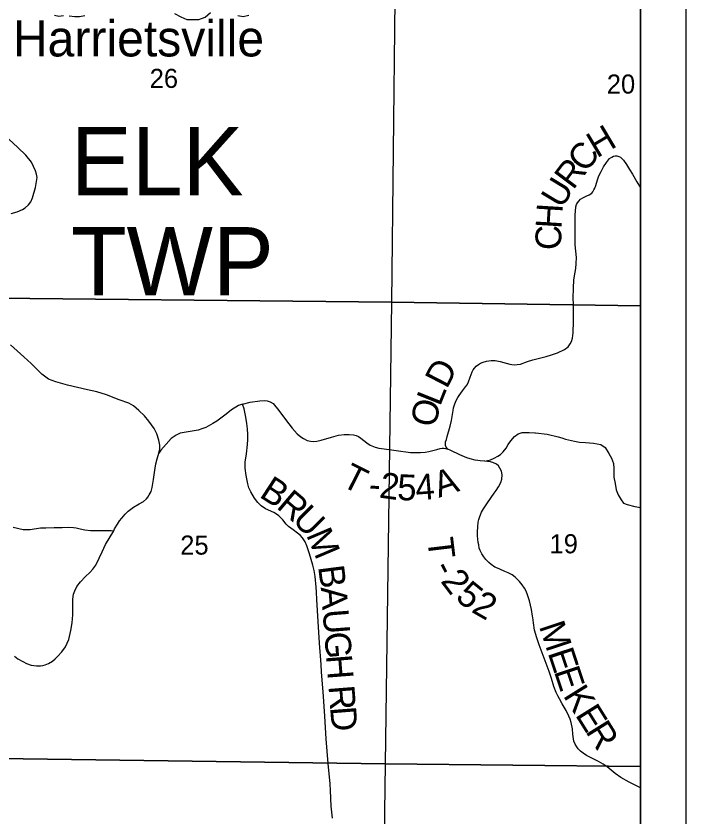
# Model space of a CAD drawing. Extents: x 0 to 34, y 0 to 22.
# Drawn here: x 7.529 to 9, y 17.691 to 19.45 of the extents above; entities that cross this region are included whole.
import ezdxf

# ---------------------------------------------------------------- set-up
doc = ezdxf.new("R2010")
doc.units = 0
for name, color, linetype in [('GM_X_Corporation', 7, 'Continuous'), ('GM_X_County_Road', 7, 'Continuous'), ('GM_X_County_Road_Text', 7, 'Continuous'), ('GM_X_Major_River', 7, 'Continuous'), ('GM_X_Section_Text', 7, 'Continuous'), ('GM_X_Township_Road', 7, 'Continuous'), ('GM_X_Township_Road_Text', 7, 'Continuous'), ('GM_X_Township_Text', 7, 'Continuous'), ('GM_X_Unincorporated_Text', 7, 'Continuous'), ('SH_Data', 7, 'Continuous')]:
    doc.layers.add(name, color=color, linetype=linetype)

msp = doc.modelspace()

# ---------------------------------------------------------------- linework, layer by layer
at = {"layer": 'GM_X_Corporation'}
for points in [[(8.3645, 19.8193), (8.353, 18.8213), (7.3418, 18.8315), (7.3548, 19.8302)], [(8.9, 18.8136), (8.9, 19.8133), (8.3645, 19.8193), (8.353, 18.8213)], [(8.353, 18.8213), (8.3394, 17.8082), (7.332, 17.8222), (7.3418, 18.8315)], [(8.9, 17.8023), (8.9, 18.8136), (8.353, 18.8213), (8.3394, 17.8082)], [(8.3394, 17.8082), (8.3265, 16.8592), (7.3376, 16.8759), (7.332, 17.8222)], [(8.9, 16.8493), (8.9, 17.8023), (8.3394, 17.8082), (8.3265, 16.8592)]]:
    msp.add_lwpolyline(points, close=True, dxfattribs=at)
at = {"layer": 'GM_X_County_Road'}
for points in [[(7.5185, 19.0165), (7.5317, 19.0201), (7.5428, 19.025), (7.5492, 19.0288), (7.5566, 19.0354), (7.5611, 19.042), (7.5653, 19.0508), (7.5717, 19.073), (7.5751, 19.0952), (7.5739, 19.1025), (7.5717, 19.1098), (7.5626, 19.1289), (7.5504, 19.1444), (7.5332, 19.1614), (7.5129, 19.1793)], [(8.2241, 17.6888), (8.2208, 17.7147), (8.2195, 17.7498), (8.2188, 17.7644), (8.2146, 17.8089), (8.2102, 17.8628), (8.2068, 17.9129), (8.2035, 17.9664), (8.2, 18.0095), (8.1989, 18.0259), (8.1956, 18.0731), (8.1926, 18.1205), (8.1897, 18.1689), (8.189, 18.1846), (8.1881, 18.1956), (8.1854, 18.2196), (8.1835, 18.2323), (8.1806, 18.2445), (8.1734, 18.2693), (8.1678, 18.2867), (8.1637, 18.2957), (8.1579, 18.3044), (8.1526, 18.3101), (8.147, 18.3147), (8.1371, 18.322), (8.1274, 18.3288), (8.1223, 18.3342), (8.1145, 18.3434), (8.1059, 18.3525), (8.1008, 18.3563), (8.0948, 18.3601), (8.0769, 18.3677), (8.0671, 18.3744), (8.0597, 18.3816), (8.0522, 18.3911), (8.0442, 18.4049), (8.0404, 18.4137), (8.0379, 18.4228), (8.0341, 18.4413), (8.0319, 18.4572), (8.0323, 18.4705), (8.0347, 18.4883), (8.0371, 18.509), (8.0376, 18.5199), (8.0377, 18.5307), (8.0373, 18.5438), (8.0358, 18.5553), (8.0337, 18.5693), (8.0296, 18.5877), (8.0261, 18.5974), (8.0176, 18.5948), (8.0019, 18.5852), (7.9906, 18.5759), (7.9785, 18.5669), (7.9695, 18.5601), (7.9614, 18.5549), (7.946, 18.5466), (7.9372, 18.5433), (7.9286, 18.5408), (7.8894, 18.5337), (7.8803, 18.5298), (7.8692, 18.5219), (7.8583, 18.5097), (7.8467, 18.4966), (7.8422, 18.4897), (7.8445, 18.4998), (7.8445, 18.5077), (7.8422, 18.5187), (7.8381, 18.5326), (7.8323, 18.5442), (7.8205, 18.5601), (7.8107, 18.5723), (7.7987, 18.5839), (7.7868, 18.5943), (7.7764, 18.5995), (7.7555, 18.6071), (7.7279, 18.6178), (7.7063, 18.6244), (7.6855, 18.6294), (7.642, 18.6392), (7.6163, 18.6464), (7.6005, 18.6528), (7.5858, 18.6636), (7.5619, 18.687), (7.5461, 18.7013), (7.517, 18.7276)]]:
    msp.add_lwpolyline(points, dxfattribs=at)
at = {"layer": 'GM_X_Major_River'}
for points in [[(7.6131, 19.4515), (7.6229, 19.4493), (7.6331, 19.4506)], [(7.6456, 19.4499), (7.6581, 19.4485), (7.668, 19.4486), (7.6801, 19.4507)], [(7.8768, 19.4554), (7.8905, 19.4476), (7.9042, 19.4424), (7.9174, 19.4418), (7.9303, 19.4419), (7.9442, 19.4474), (7.9562, 19.4578)], [(8.0161, 19.4512), (8.0279, 19.4487), (8.0403, 19.4518)]]:
    msp.add_lwpolyline(points, dxfattribs=at)
at = {"layer": 'GM_X_Township_Road'}
for points in [[(8.4768, 18.4991), (8.4733, 18.5035), (8.4719, 18.5068), (8.4716, 18.5106), (8.472, 18.5148), (8.4738, 18.52), (8.4759, 18.5263), (8.4824, 18.5495), (8.4851, 18.5615), (8.4866, 18.5705), (8.4887, 18.5835), (8.4896, 18.5894), (8.4907, 18.5941), (8.4922, 18.5986), (8.495, 18.6053), (8.4989, 18.6124), (8.5019, 18.6166), (8.5096, 18.627), (8.5162, 18.6353), (8.5195, 18.6402), (8.5224, 18.6466), (8.5261, 18.6569), (8.5304, 18.6685), (8.5326, 18.6729), (8.5353, 18.6767), (8.5392, 18.6807), (8.5442, 18.6848), (8.5485, 18.6876), (8.5543, 18.6901), (8.5619, 18.6921), (8.5719, 18.6935), (8.5812, 18.6933), (8.5922, 18.6912), (8.6052, 18.6879), (8.6135, 18.6856), (8.6177, 18.6849), (8.6234, 18.6843), (8.6292, 18.6844), (8.6363, 18.6856), (8.6521, 18.691), (8.6635, 18.6949), (8.6783, 18.6988), (8.6929, 18.7026), (8.7045, 18.7056), (8.7181, 18.71), (8.7334, 18.7174), (8.7415, 18.7237), (8.746, 18.73), (8.7486, 18.7352), (8.751, 18.7425), (8.7524, 18.7541), (8.753, 18.7799), (8.7527, 18.8173), (8.7526, 18.8305), (8.7528, 18.8526), (8.754, 18.8702), (8.7564, 18.8872), (8.7578, 18.8954), (8.7592, 18.9061), (8.7594, 18.9196), (8.757, 18.9471), (8.7564, 19.0012), (8.7566, 19.0133), (8.7573, 19.0216), (8.7584, 19.0306), (8.7599, 19.0356), (8.7618, 19.0395), (8.7648, 19.0435), (8.7686, 19.0473), (8.7738, 19.0507), (8.7825, 19.0549), (8.7877, 19.0574), (8.793, 19.0609), (8.7958, 19.0641), (8.798, 19.0681), (8.7997, 19.0721), (8.8018, 19.0774), (8.8056, 19.0901), (8.8089, 19.0986), (8.8136, 19.1081), (8.819, 19.1188), (8.8253, 19.1285), (8.8324, 19.1366), (8.8369, 19.1402), (8.8406, 19.1417), (8.8445, 19.1425), (8.8483, 19.1425), (8.8527, 19.1414), (8.8561, 19.1395), (8.8595, 19.137), (8.8629, 19.1334), (8.8697, 19.1234), (8.8758, 19.1131), (8.8822, 19.1027), (8.8924, 19.0855), (8.9, 19.0722)], [(8.0261, 18.5974), (8.0427, 18.6019), (8.0639, 18.6051), (8.0742, 18.6059), (8.0804, 18.6051), (8.0868, 18.6025), (8.0933, 18.5987), (8.1061, 18.5834), (8.1203, 18.5641), (8.1351, 18.5448), (8.146, 18.5328), (8.1542, 18.5262), (8.1604, 18.5219), (8.1681, 18.518), (8.1758, 18.5163), (8.1818, 18.5157), (8.1895, 18.5163), (8.1986, 18.5185), (8.2214, 18.5254), (8.2372, 18.5292), (8.2491, 18.5309), (8.2604, 18.531), (8.2701, 18.5302), (8.2757, 18.5287), (8.281, 18.5266), (8.2863, 18.5233), (8.2995, 18.5129), (8.3065, 18.5079), (8.3174, 18.5034), (8.3256, 18.5013), (8.3369, 18.4993), (8.3635, 18.496), (8.395, 18.4915), (8.4173, 18.4915), (8.4272, 18.4925), (8.4357, 18.4937), (8.4443, 18.4956), (8.453, 18.4984), (8.4601, 18.5003), (8.4644, 18.5011), (8.4681, 18.5013), (8.4718, 18.5006), (8.4768, 18.4991)], [(8.5585, 18.4726), (8.5642, 18.4736), (8.5707, 18.4753), (8.579, 18.479), (8.5871, 18.4835), (8.5926, 18.4871), (8.5986, 18.4928), (8.6054, 18.501), (8.6097, 18.5094), (8.6154, 18.5171), (8.6234, 18.5265), (8.6316, 18.5327), (8.6401, 18.5354), (8.6554, 18.5354), (8.6678, 18.5345), (8.6692, 18.5344)], [(8.6692, 18.5344), (8.6954, 18.5317), (8.719, 18.5258), (8.7272, 18.5234), (8.7353, 18.5206), (8.7554, 18.5161), (8.766, 18.5139), (8.779, 18.5135), (8.7966, 18.5117), (8.8127, 18.5091), (8.8228, 18.5024), (8.8309, 18.4892), (8.8361, 18.4788), (8.841, 18.4677), (8.8419, 18.456), (8.8419, 18.4371), (8.8445, 18.4235), (8.8467, 18.4096), (8.8508, 18.3988), (8.8579, 18.3877), (8.863, 18.3804), (8.871, 18.3771), (8.8876, 18.3727), (8.9, 18.3706)], [(8.5585, 18.4726), (8.5477, 18.4731), (8.5428, 18.4737), (8.537, 18.4748), (8.526, 18.4776), (8.519, 18.48), (8.5037, 18.4865), (8.4833, 18.496), (8.4768, 18.4991)], [(7.5257, 18.0444), (7.5331, 18.0388), (7.5438, 18.0325), (7.552, 18.0283), (7.5624, 18.0248), (7.574, 18.0233), (7.5828, 18.0231), (7.5881, 18.024), (7.5932, 18.0256), (7.6005, 18.0284), (7.6087, 18.0333), (7.6145, 18.0384), (7.6198, 18.0436), (7.6295, 18.0537), (7.6373, 18.0645), (7.6449, 18.0806), (7.6496, 18.1007), (7.6522, 18.1172), (7.6536, 18.135), (7.6539, 18.1471), (7.6535, 18.1588), (7.6535, 18.1693), (7.6553, 18.1802), (7.6577, 18.1876), (7.6622, 18.1971), (7.6702, 18.2076), (7.6814, 18.2192), (7.6906, 18.228), (7.6978, 18.235), (7.704, 18.244), (7.7116, 18.2598), (7.7178, 18.2736), (7.7255, 18.2896), (7.7435, 18.3194), (7.7454, 18.3238), (7.7515, 18.3343), (7.7561, 18.3414), (7.761, 18.3473), (7.7647, 18.352), (7.7688, 18.3563), (7.7754, 18.3626), (7.7811, 18.3673), (7.7872, 18.3716), (7.799, 18.3788), (7.8085, 18.3838), (7.8155, 18.3898), (7.8185, 18.3935), (7.8216, 18.3986), (7.8253, 18.4058), (7.828, 18.4149), (7.831, 18.4323), (7.8328, 18.4477), (7.8362, 18.4664), (7.8388, 18.4777), (7.8422, 18.4897)], [(8.6633, 18.1321), (8.6608, 18.147), (8.6567, 18.1658), (8.6523, 18.1792), (8.649, 18.1869), (8.6452, 18.1937), (8.64, 18.2013), (8.6345, 18.2082), (8.63, 18.2128), (8.6251, 18.2177), (8.6183, 18.2229), (8.6095, 18.2275), (8.6023, 18.2306), (8.591, 18.2352), (8.5858, 18.2372), (8.5806, 18.24), (8.5722, 18.2457), (8.567, 18.25), (8.5606, 18.2567), (8.5561, 18.2625), (8.5517, 18.2692), (8.548, 18.276), (8.5462, 18.2818), (8.5449, 18.2886), (8.5436, 18.2941), (8.5424, 18.3082), (8.5425, 18.3176), (8.5428, 18.3282), (8.544, 18.3389), (8.5452, 18.3444), (8.5474, 18.3507), (8.5513, 18.3606), (8.5554, 18.3679), (8.5641, 18.3809), (8.579, 18.4023), (8.5833, 18.4084), (8.5883, 18.4163), (8.5932, 18.4257), (8.5953, 18.433), (8.5961, 18.4424), (8.595, 18.4504), (8.5916, 18.4572), (8.5884, 18.462), (8.5837, 18.4656), (8.576, 18.4695), (8.5679, 18.4714), (8.5639, 18.472), (8.5585, 18.4726)], [(7.5228, 18.3273), (7.5444, 18.3226), (7.5601, 18.3226), (7.5826, 18.3259), (7.5946, 18.3262), (7.6126, 18.3266), (7.6299, 18.3272), (7.645, 18.3274), (7.655, 18.327), (7.6611, 18.3259), (7.6697, 18.3241), (7.6798, 18.322), (7.6921, 18.3205), (7.7075, 18.32), (7.7309, 18.3202), (7.7375, 18.3202), (7.7435, 18.3194)], [(8.9, 17.7551), (8.8756, 17.7676), (8.8571, 17.7778), (8.8445, 17.7867), (8.8266, 17.8016), (8.8182, 17.8072), (8.8079, 17.8129), (8.792, 17.8211), (8.7816, 17.8264), (8.7745, 17.8313), (8.7681, 17.836), (8.7634, 17.8408), (8.7602, 17.8451), (8.7563, 17.851), (8.7539, 17.8579), (8.7514, 17.8732), (8.7506, 17.8852), (8.748, 17.8985), (8.7458, 17.9059), (8.7428, 17.9128), (8.7367, 17.9251), (8.7279, 17.9399), (8.7221, 17.9507), (8.7183, 17.9571), (8.7149, 17.9648), (8.7095, 17.9778), (8.7044, 17.9952), (8.6997, 18.0107), (8.6954, 18.0225), (8.6776, 18.0693), (8.6722, 18.0848), (8.6677, 18.1017), (8.6652, 18.1175), (8.6638, 18.1293), (8.6633, 18.1321)]]:
    msp.add_lwpolyline(points, dxfattribs=at)
at = {"layer": 'GM_X_Township_Text'}
msp.add_lwpolyline([(8.9, 16.8499), (8.9, 20.9), (6.4827, 20.9)], dxfattribs=at)
at = {"layer": 'SH_Data'}
for p, q in [((9, 21), (9, 14)), ((8.9, 20.9), (8.9, 14.1))]:
    msp.add_line(p, q, dxfattribs=at)

# ---------------------------------------------------------------- texts
at = {"layer": 'GM_X_County_Road_Text'}
for s, rotation, p in [('B', 326.8382, (8.0609, 18.3953)), ('R', 319.6857, (8.0985, 18.3709)), ('U', 315.0515, (8.1332, 18.3415)), ('M', 292.9632, (8.1654, 18.3109)), ('B', 277.2712, (8.1921, 18.241)), ('A', 274.5728, (8.1979, 18.1954)), ('U', 274.4415, (8.2019, 18.1456)), ('G', 274.4416, (8.2058, 18.0958)), ('H', 274.4433, (8.2096, 18.0459)), ('R', 274.4421, (8.2149, 17.9786)), ('D', 274.4416, (8.2185, 17.9321))]:
    msp.add_text(s, height=0.0568, rotation=rotation, dxfattribs=at).set_placement(p)
at = {"layer": 'GM_X_Section_Text'}
for s, p in [('26', (7.8224, 19.2919)), ('20', (8.8262, 19.2794)), ('25', (7.8895, 18.2673)), ('19', (8.7004, 18.2702))]:
    msp.add_text(s, height=0.04186, rotation=0, dxfattribs=at).set_placement(p)
at = {"layer": 'GM_X_Township_Road_Text'}
for s, rotation, p in [('H', 30.762, (8.8043, 19.1369)), ('C', 52.7593, (8.7803, 19.1036)), ('R', 53.0911, (8.7523, 19.0663)), ('U', 58.8163, (8.7273, 19.0248)), ('H', 86.4241, (8.7263, 18.9817)), ('C', 89.9688, (8.7263, 18.936)), ('D', 62.6383, (8.4748, 18.6293)), ('L', 68.2225, (8.4597, 18.5911)), ('O', 77.9185, (8.4499, 18.5447)), ('T', 333.3104, (8.2405, 18.4196)), ('2', 352.154, (8.3247, 18.3927)), ('A', 18.2701, (8.4571, 18.3917)), ('5', 357.443, (8.3651, 18.3874)), ('4', 4.6041, (8.4078, 18.386)), ('-', 356.4423, (8.3025, 18.394)), ('T', 276.8561, (8.4318, 18.3017)), ('-', 297.3113, (8.4434, 18.2385)), ('2', 307.2358, (8.4598, 18.2087)), ('5', 320.9595, (8.4913, 18.1702)), ('2', 330.1703, (8.5267, 18.1425)), ('M', 288.3369, (8.6767, 18.1103)), ('E', 288.332, (8.6961, 18.0518)), ('E', 288.445, (8.7095, 18.0113)), ('K', 301.9567, (8.7291, 17.958)), ('E', 302.0615, (8.7556, 17.9155)), ('R', 302.0087, (8.7782, 17.8795))]:
    msp.add_text(s, height=0.0568, rotation=rotation, dxfattribs=at).set_placement(p)
at = {"layer": 'GM_X_Township_Text'}
for s, p in [('ELK', (7.6492, 19.0563)), ('TWP', (7.6492, 18.8363))]:
    msp.add_text(s, height=0.15, rotation=0, dxfattribs=at).set_placement(p)
at = {"layer": 'GM_X_Unincorporated_Text'}
msp.add_text('Harrietsville', height=0.078977, rotation=0, dxfattribs=at).set_placement((7.522, 19.361))

doc.saveas('drawing.dxf')
